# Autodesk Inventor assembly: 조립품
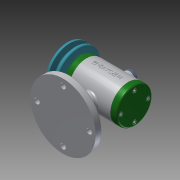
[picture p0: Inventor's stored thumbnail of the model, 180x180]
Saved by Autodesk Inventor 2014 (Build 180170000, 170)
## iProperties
Created: 2018-12
Part Number: 조립품
Document SubType Name: Assembly
Designer: 601-21
Author: 601-21
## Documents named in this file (15)
- C:\Users\601-21\Desktop\481208V1004\조립품.iam
- C:\Users\601-21\Desktop\481208V1004\본체.ipt
- C:\Users\601-21\Desktop\481208V1004\V벨트풀리.ipt
- C:\Users\601-21\Desktop\481208V1004\고무캡.ipt
- C:\Users\601-21\Desktop\481208V1004\너트 M8.ipt
- 너트 M8.ipt
- C:\Users\601-21\Desktop\481208V1004\뒤커버.ipt
- C:\Users\601-21\Desktop\481208V1004\베어링 15 x 32 x 9.ipt
- C:\Users\601-21\Desktop\481208V1004\볼트 M4 x 12.ipt
- C:\Users\601-21\Desktop\481208V1004\스프링와셔 8.ipt
- C:\Users\601-21\Desktop\481208V1004\앞커버.ipt
- C:\Users\601-21\Desktop\481208V1004\오일 실 15 25 7.ipt
- C:\Users\601-21\Desktop\481208V1004\와셔 8x17.ipt
- C:\Users\601-21\Desktop\481208V1004\축.ipt
- C:\Users\601-21\Desktop\481208V1004\키 3 x 3 x 12.ipt
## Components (2 placed, 2 different names)
1. V벨트풀리:1
2. 고무캡:1
